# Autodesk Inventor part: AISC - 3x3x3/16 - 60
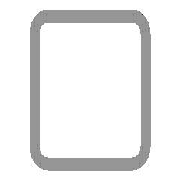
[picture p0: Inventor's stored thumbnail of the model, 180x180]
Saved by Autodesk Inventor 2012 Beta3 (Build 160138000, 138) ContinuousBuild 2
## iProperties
Created: 2010-11
Part Number: AISC - 3x3x3/16 - 60
Material: Steel, Mild
Description: Tube
Document SubType Name: Modeling
Standard: ANSI
Designer: Beta-8540w
Standards Organization: ANSI
Language: en-US
Size Designation: 3x3x3/16
Categories: <MemberInstance><Categories><Category DisplayName="Structural Shapes" InternalName="089c4875-fa83-4c05-b084-43b9cc11f5ed" Mnemonic="GRDR"><CategoryParameter Dis
Stock Number: 3x3x3/16
Density: 7.86 g/cm^3
IsCustomPart: 1
_CCFamilyMember: 9
_CCFamilyDisplayName: ANSI AISC (Square) - Tube
_FrameMemberDoc: Frame Member File
_Version: 15.0.0
_GetPNFromCC: 1
G_L: 60.000 in
G_W: 3.000 in
G_H: 3.000 in
Author: Beta-8540w
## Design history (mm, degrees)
node "Start plane"
node "End plane"
sketch "Sketch"
  geometry: L1 (-38.1, -28.575)-(-38.1, 28.575); L2 (-28.575, 38.1)-(28.575, 38.1); L3 (38.1, 28.575)-(38.1, -28.575); L4 (28.575, -38.1)-(-28.575, -38.1); L5 (-28.575, 33.337)-(28.575, 33.338); L6 (33.338, 28.575)-(33.338, -28.575); L7 (28.575, -33.337)-(-28.575, -33.338); L8 (-33.338, -28.575)-(-33.338, 28.575); L9 (0, 56.102)-(0, -56.102) reference; L10 (-56.102, 0)-(56.102, 0) reference; A1 r 9.525 centre (-28.575, -28.575) between (-38.1, -28.575) and (-28.575, -38.1); A2 r 9.525 centre (-28.575, 28.575) between (-28.575, 38.1) and (-38.1, 28.575); A3 r 9.525 centre (28.575, 28.575) between (38.1, 28.575) and (28.575, 38.1); A4 r 9.525 centre (28.575, -28.575) between (28.575, -38.1) and (38.1, -28.575); A5 r 4.763 centre (-28.575, 28.575) between (-28.575, 33.337) and (-33.338, 28.575); A6 r 4.763 centre (28.575, 28.575) between (33.338, 28.575) and (28.575, 33.338); A7 r 4.763 centre (28.575, -28.575) between (28.575, -33.337) and (33.338, -28.575); A8 r 4.763 centre (-28.575, -28.575) between (-33.338, -28.575) and (-28.575, -33.338)
  constraints: 16 end point, 16 point on circle, 8 centre point, 8 tangent, 4 parallel, 3 equal radius, 2 perpendicular, 7 other
  dimensions: "d10" = 76.2 distance between parallel lines of L2 L4 (= G_H); "d11" = 76.2 distance between parallel lines of L1 L3 (= G_W); "d12" = 4.7625 distance between parallel lines of L3 L6 (= G_T); "d15" = 38.1 distance between parallel lines of L2 L10 (= 0.5 x d10); "d16" = 38.1 distance between parallel lines of L9 L3 (= 0.5 x d11); "d17" = 9.525 radius of A1 (= G_IR)
extrude "Body" new body sketch "Sketch" stored distance "d3" = 1524 (= G_L); taper "d4" = 0 deg
node "Driven Length"
  sketch "Sketch3"
    geometry: L1 (0, 0)-(10, 0) reference
    constraints: 2 end point, 1 horizontal
  workplane "Work Plane3"
  sketch "Sketch4"
    geometry: L1 (-2, 0)-(12, 0) reference; L2 (-2, 1524)-(12, 1524) reference
    dimensions: "d19" = 1524 distance between parallel lines of L1 L2 (derived)
body "Solid1"
other parameters: "G_W" = 76.2 [user parameter; used in 1 equation term], "G_H" = 76.2 [user parameter; used in 1 equation term], "G_T" = 4.7625 [user parameter; used in 1 equation term], "G_IR" = 9.525 [user parameter; used in 1 equation term], "G_L" = 1524 (= d19) [user parameter; used in 1 equation term], "G_OFFSET_START" = 0 [user parameter; used in 1 equation term], "G_OFFSET_END" = 0 [user parameter; used in 1 equation term], "d13" = 0 (computed from G_OFFSET_START), "d14" = 1524 (= G_OFFSET_END + B_L), "B_L" = 1524 [user parameter; used in 1 equation term], "d18" = 90 deg
